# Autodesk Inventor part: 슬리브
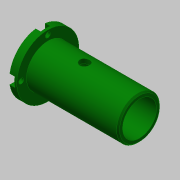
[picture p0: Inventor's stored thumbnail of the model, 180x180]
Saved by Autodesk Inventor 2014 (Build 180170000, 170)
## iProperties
Created: 2019-10
Part Number: 슬리브
Material: 알루미늄 6061
Document SubType Name: Modeling
Designer: mduedu
Density: 1 g/cm^3
Appearance: 진녹색
Author: mduedu
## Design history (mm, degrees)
sketch "스케치1"
  geometry: L1 (0, 0)-(5, 0); L2 (5, 0)-(5, 21); L3 (5, 21)-(0, 21); L4 (0, 21)-(0, 0); L5 (5, 0)-(67, 0); L6 (67, 0)-(67, 14.5); L7 (67, 14.5)-(5, 14.5); L8 (5, 14.5)-(5, 0)
  constraints: 16 end point, 4 parallel, 2 horizontal, 2 perpendicular
  dimensions: "d0" = 67 distance between parallel lines of L6 L4; "d2" = 62 distance of L6.end L7.end; "d3" = 42 diameter of L3 L1; "d4" = 29 diameter of L7 L5
revolve "회전1" sketch "스케치1" stored, may be unused: angle "d5" = 90 deg
hole "구멍1" diameter "d8" = 23; stored, may be unused: countersink angle "d12" = 90 deg, drill point angle "d14" = 118 deg; dims "d6" = 10, "d7" = 10, "d9" = 6, "d10" = 4, "d11" = 2, "d13" = 8
sketch "스케치2"
  geometry: L1 (-5, 21)-(-5, -21) reference; C1 r 3.3 at (-30, 0); 1 further point
  constraints: 1 centre point, 1 horizontal alignment
  dimensions: "d15" = 6.6 diameter of C1; "d16" = 25 distance from line of C1.centre L1
extrude "돌출1" cut sketch "스케치2" stored distance "d17" = 10; taper "d18" = 0 deg
chamfer "모따기1" distance "d19" = 1; stored, may be unused: second distance "d20" = 2, angle "d21" = 45 deg
sketch "스케치3" dims "d22" = 36
  geometry: 6 further points
  constraints: 2 vertical alignment, 1 coincident, 7 other
  dimensions: "d25" = 360 deg dimension on point (0, 0) point (0, 18) (derived)
sketch "스케치4"
  geometry: 4 further points
  constraints: 4 other
hole "구멍2" sketch "스케치4" at (-18, 0), (0, -18), (18, 0), (0, 18) diameter "d27" = 3.4; stored, may be unused: countersink angle "d31" = 90 deg, drill point angle "d33" = 0 deg; dims "d28" = 6, "d29" = 6.5, "d30" = 3.4, "d32" = 8
sketch "스케치5"
  geometry: L1 (-21.25, 20.747)-(-21.25, 18); L2 (-14.75, 18)-(-14.75, 20.747); A1 r 3.25 centre (-18, 18) between (-19.349, 20.957) and (-16.651, 20.957) reference; A2 r 21 centre (-18, 0) between (-19.349, 20.957) and (-38.957, 1.349) reference; A3 r 21 centre (-18, 0) between (2.957, 1.349) and (-16.651, 20.957) reference; A4 r 21 centre (-18, 0) between (-14.75, 20.747) and (-21.25, 20.747); A5 r 3.25 centre (-18, 18) between (-21.25, 18) and (-14.75, 18); 1 further point
  constraints: 8 point on circle, 4 end point, 2 centre point, 2 coincident, 2 tangent, 1 parallel, 1 vertical
extrude "돌출2" cut sketch "스케치5" stored distance "d34" = 10; taper "d35" = 0 deg
node "솔리드1"
pattern_circular "원형 패턴1" dims angle "d37" = 360 deg
